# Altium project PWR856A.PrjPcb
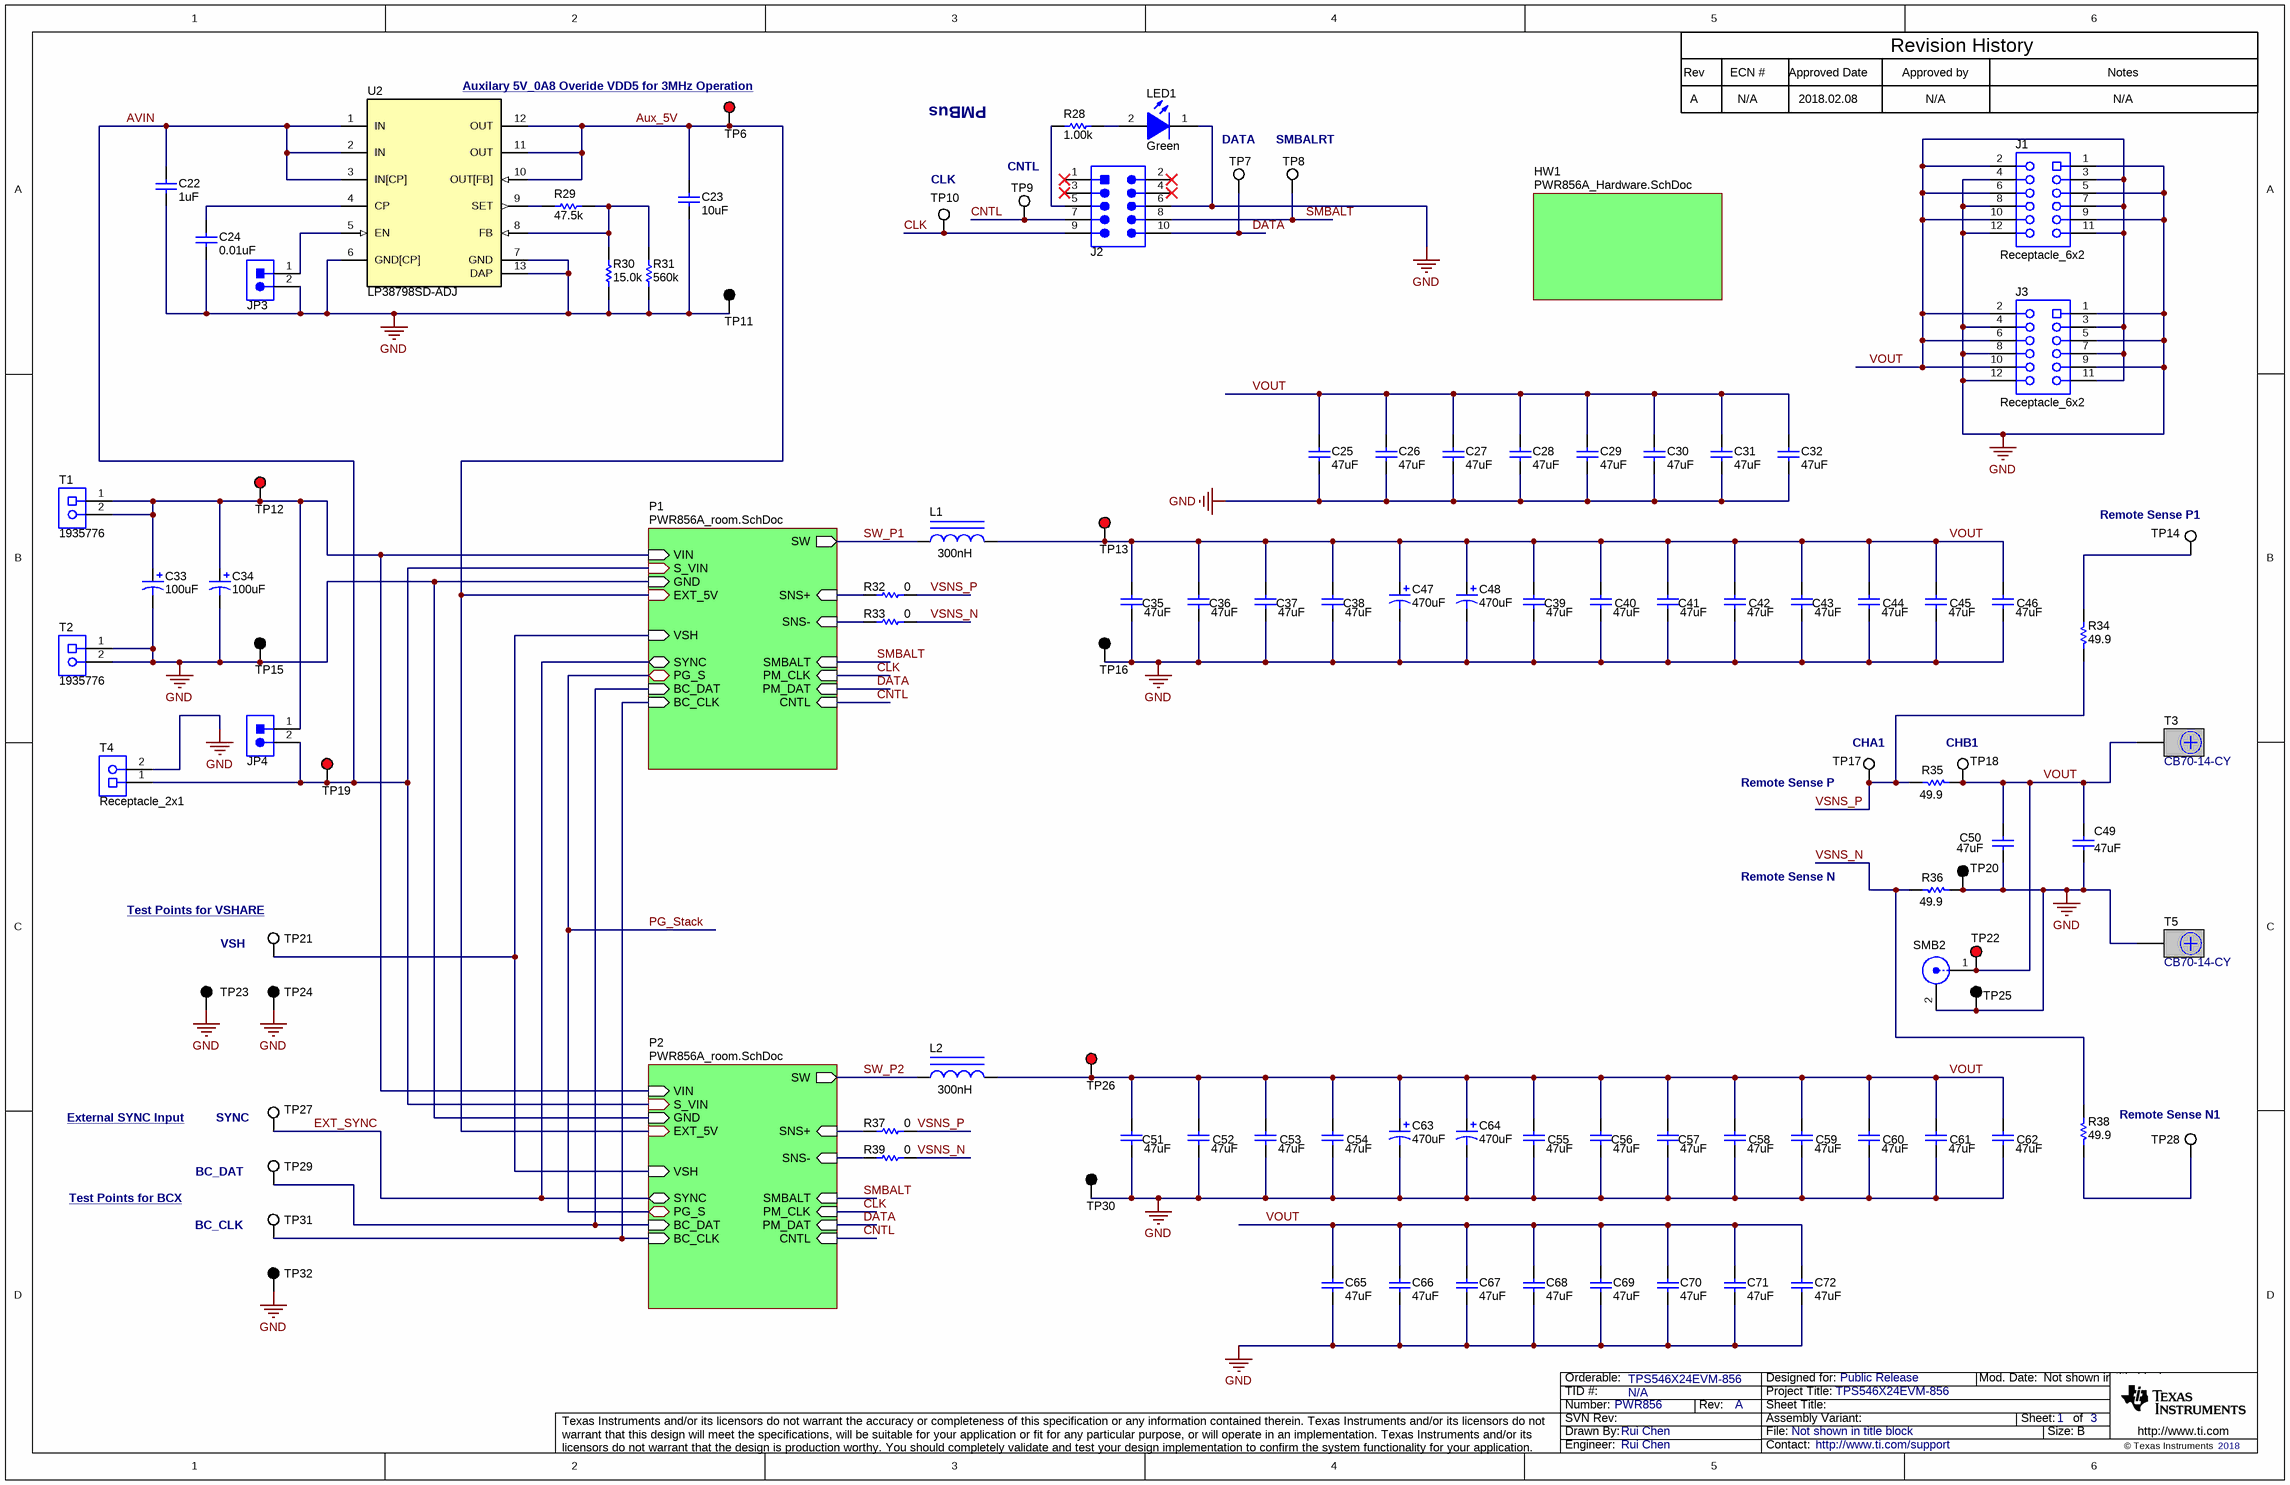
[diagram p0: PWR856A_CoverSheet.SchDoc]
CopyrightYear: 2018; EVM_orderable: TPS546X24EVM-856; PCB_Layout: Rui Chen; PCB_Rev: A; PRJ_Customer: Public Release; PRJ_Engineer: Rui Chen; PRJ_Number: PWR856; PRJ_Title: TPS546X24EVM-856; SCH_Rev: A; TechSupport: http://www.ti.com/support; TID: N/A
3 sheets, 253 parts. Net scope: strictly hierarchical (ports join the sheet entries above them; power ports are local).
Board file: PWR856A.PcbDoc
Sheets:
  PWR856A_CoverSheet.SchDoc
    P1 = PWR856A_room.SchDoc
    P2 = PWR856A_room.SchDoc
    HW1 = PWR856A_Hardware.SchDoc

## Sheet PWR856A_CoverSheet.SchDoc
size 431 x 279 mm; Date: Not shown in title block; ApprovedBy: Not shown in title block; CheckedBy: Not shown in title block; Author: Not shown in title block; CompanyName: Not shown in title block; DrawnBy: Rui Chen; Engineer: Not shown in title block; Organization: Not shown in title block; Address1: Not shown in title block; Address2: Not shown in title block; Address3: Not shown in title block; Address4: Not shown in title block; DocumentNumber: 1; Revision: Use project parameter SCH_Rev; SheetNumber: 1; SheetTotal: 3; PageSetup: Record=PageOptions¦CenterHorizontal=True¦CenterVertical=True¦PrintScale=1.00¦XCorrection=1.00¦YCorrection=1.00¦PrintKind=0¦BorderSize=5000000¦LeftOffset=0¦BottomOffset=0¦Orientation=2¦PaperLength=1000¦PaperWidth=1000¦Scale=100¦PaperSource=15¦PrintQuality=600¦MediaType=1¦DitherType=10¦PaperKind=Letter¦PrintScaleMode=1

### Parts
C22  ValueDisplayed: 1uF  [0805_HV]  (hidden comment: Capacitor)
C23  ValueDisplayed: 10uF  [0805_HV]  (hidden comment: Capacitor)
C24  ValueDisplayed: 0.01uF  [0603L]  (hidden comment: Capacitor)
C25  ValueDisplayed: 47uF  [1210_270]  (hidden comment: Capacitor)
C26  ValueDisplayed: 47uF  [1210_270]  (hidden comment: Capacitor)
C27  ValueDisplayed: 47uF  [1210_270]  (hidden comment: Capacitor)
C28  ValueDisplayed: 47uF  [1210_270]  (hidden comment: Capacitor)
C29  ValueDisplayed: 47uF  [1210_270]  (hidden comment: Capacitor)
C30  ValueDisplayed: 47uF  [1210_270]  (hidden comment: Capacitor)
C31  ValueDisplayed: 47uF  [1210_270]  (hidden comment: Capacitor)
C32  ValueDisplayed: 47uF  [1210_270]  (hidden comment: Capacitor)
C33  ValueDisplayed: 100uF  [SM_RADIAL_G]  (hidden comment: Cap_Polarized)
C34  ValueDisplayed: 100uF  [SM_RADIAL_G]  (hidden comment: Cap_Polarized)
C35  ValueDisplayed: 47uF  [1210_270]  (hidden comment: Capacitor)
C36  ValueDisplayed: 47uF  [1210_270]  (hidden comment: Capacitor)
C37  ValueDisplayed: 47uF  [1210_270]  (hidden comment: Capacitor)
C38  ValueDisplayed: 47uF  [1210_270]  (hidden comment: Capacitor)
C39  ValueDisplayed: 47uF  [1210_270]  (hidden comment: Capacitor)
C40  ValueDisplayed: 47uF  [1210_270]  (hidden comment: Capacitor)
C41  ValueDisplayed: 47uF  [1210_270]  (hidden comment: Capacitor)
C42  ValueDisplayed: 47uF  [1210_270]  (hidden comment: Capacitor)
C43  ValueDisplayed: 47uF  [1210_270]  (hidden comment: Capacitor)
C44  ValueDisplayed: 47uF  [1210_270]  (hidden comment: Capacitor)
C45  ValueDisplayed: 47uF  [1210_270]  (hidden comment: Capacitor)
C46  ValueDisplayed: 47uF  [1210_270]  (hidden comment: Capacitor)
C47  ValueDisplayed: 470uF  [7343-40]  (hidden comment: Cap_Polarized)
C48  ValueDisplayed: 470uF  [7343-40]  (hidden comment: Cap_Polarized)
C49  ValueDisplayed: 47uF  [1210_270]  (hidden comment: Capacitor)
C50  ValueDisplayed: 47uF  [1210_270]  (hidden comment: Capacitor)
C51  ValueDisplayed: 47uF  [1210_270]  (hidden comment: Capacitor)
C52  ValueDisplayed: 47uF  [1210_270]  (hidden comment: Capacitor)
C53  ValueDisplayed: 47uF  [1210_270]  (hidden comment: Capacitor)
C54  ValueDisplayed: 47uF  [1210_270]  (hidden comment: Capacitor)
C55  ValueDisplayed: 47uF  [1210_270]  (hidden comment: Capacitor)
C56  ValueDisplayed: 47uF  [1210_270]  (hidden comment: Capacitor)
C57  ValueDisplayed: 47uF  [1210_270]  (hidden comment: Capacitor)
C58  ValueDisplayed: 47uF  [1210_270]  (hidden comment: Capacitor)
C59  ValueDisplayed: 47uF  [1210_270]  (hidden comment: Capacitor)
C60  ValueDisplayed: 47uF  [1210_270]  (hidden comment: Capacitor)
C61  ValueDisplayed: 47uF  [1210_270]  (hidden comment: Capacitor)
C62  ValueDisplayed: 47uF  [1210_270]  (hidden comment: Capacitor)
C63  ValueDisplayed: 470uF  [7343-40]  (hidden comment: Cap_Polarized)
C64  ValueDisplayed: 470uF  [7343-40]  (hidden comment: Cap_Polarized)
C65  ValueDisplayed: 47uF  [1210_270]  (hidden comment: Capacitor)
C66  ValueDisplayed: 47uF  [1210_270]  (hidden comment: Capacitor)
C67  ValueDisplayed: 47uF  [1210_270]  (hidden comment: Capacitor)
C68  ValueDisplayed: 47uF  [1210_270]  (hidden comment: Capacitor)
C69  ValueDisplayed: 47uF  [1210_270]  (hidden comment: Capacitor)
C70  ValueDisplayed: 47uF  [1210_270]  (hidden comment: Capacitor)
C71  ValueDisplayed: 47uF  [1210_270]  (hidden comment: Capacitor)
C72  ValueDisplayed: 47uF  [1210_270]  (hidden comment: Capacitor)
J1  Receptacle_6x2  [Samtec_SSW-106-23-x-D]
J2  Header_5x2  [CONN_5103308-1]  (value not drawn)
J3  Receptacle_6x2  [Samtec_SSW-106-23-x-D]
JP3  Header_2x1  [TE_5-146278-2]  (value not drawn)
JP4  Header_2x1  [TE_5-146278-2]  (value not drawn)
L1  value 300nH  [SLC1480]  (hidden comment: Inductor_Iron)
L2  value 300nH  [SLC1480]  (hidden comment: Inductor_Iron)
LED1  value Green  [WL-SMCW_GREEN]  (hidden comment: LED_A2_K1)
R28  ValueDisplayed: 1.00k  [0603L]  (hidden comment: Resistor)
R29  ValueDisplayed: 47.5k  [0603L]  (hidden comment: Resistor)
R30  ValueDisplayed: 15.0k  [0603L]  (hidden comment: Resistor)
R31  ValueDisplayed: 560k  [0603L]  (hidden comment: Resistor)
R32  value 0  [0603L]  (hidden comment: Resistor)
R33  value 0  [0603L]  (hidden comment: Resistor)
R34  value 49.9  [0603L]  (hidden comment: Resistor)
R35  value 49.9  [0603L]  (hidden comment: Resistor)
R36  value 49.9  [0603L]  (hidden comment: Resistor)
R37  value 0  [0603L]  (hidden comment: Resistor)
R38  value 49.9  [0603L]  (hidden comment: Resistor)
R39  value 0  [0603L]  (hidden comment: Resistor)
SMB2  SMA_Contact1_GND2  [JAE_SMBR004D00]  (value not drawn)
T1  1935776  [Phoenix_1935776]
T2  1935776  [Phoenix_1935776]
T3  CB70-14-CY  [CB70-14-CY]
T4  Receptacle_2x1  [TERM_BLK_ED555-2DS]
T5  CB70-14-CY  [CB70-14-CY]
TP6  5010  [Keystone5010]  (value not drawn)
TP7  5012  [Keystone5012]  (value not drawn)
TP8  5012  [Keystone5012]  (value not drawn)
TP9  5012  [Keystone5012]  (value not drawn)
TP10  5012  [Keystone5012]  (value not drawn)
TP11  5011  [Keystone5011]  (value not drawn)
TP12  5010  [Keystone5010]  (value not drawn)
TP13  5010  [Keystone5010]  (value not drawn)
TP14  5010  [Keystone5012]  (value not drawn)
TP15  5011  [Keystone5011]  (value not drawn)
TP16  5011  [Keystone5011]  (value not drawn)
TP17  5012  [Keystone5012]  (value not drawn)
TP18  5012  [Keystone5012]  (value not drawn)
TP19  5010  [Keystone5010]  (value not drawn)
TP20  5011  [Keystone5011]  (value not drawn)
TP21  5012  [Keystone5012]  (value not drawn)
TP22  5012  [Keystone5010]  (value not drawn)
TP23  5011  [Keystone5011]  (value not drawn)
TP24  5011  [Keystone5011]  (value not drawn)
TP25  5011  [Keystone5011]  (value not drawn)
TP26  5010  [Keystone5010]  (value not drawn)
TP27  5012  [Keystone5012]  (value not drawn)
TP28  5011  [Keystone5012]  (value not drawn)
TP29  5012  [Keystone5012]  (value not drawn)
TP30  5011  [Keystone5011]  (value not drawn)
TP31  5012  [Keystone5012]  (value not drawn)
TP32  5011  [Keystone5011]  (value not drawn)
U2  LP38798SD-ADJ  [DNT0012B]

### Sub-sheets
HW1 = PWR856A_Hardware.SchDoc: no entries
P1 = PWR856A_room.SchDoc: SNS+ (in), SMBALT (in), PM_CLK (in), PM_DAT (in), BC_CLK (in), BC_DAT (in), VIN, GND, SNS- (in), SW, VSH (in), SYNC (bidir), CNTL (in), S_VIN, EXT_5V (in), PG_S (bidir)
P2 = PWR856A_room.SchDoc: SNS+ (in), SMBALT (in), PM_CLK (in), PM_DAT (in), BC_CLK (in), BC_DAT (in), VIN, GND, SNS- (in), SW, VSH (in), SYNC (bidir), CNTL (in), S_VIN, EXT_5V (in), PG_S (bidir)

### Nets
GND: C22.2 C23.2 C24.2 C25.2 C26.2 C27.2 C28.2 C29.2 C30.2 C31.2 C32.2 C33.2(-) C34.2(-) C35.1 C36.1 C37.1 C38.1 C39.1 C40.1 C41.1 C42.1 C43.1 C44.1 C45.1 C46.1 C47.2(-) C48.2(-) C49.1 C50.1 C51.1 C52.1 C53.1 C54.1 C55.1 C56.1 C57.1 C58.1 C59.1 C60.1 C61.1 C62.1 C63.2(-) C64.2(-) C65.2 C66.2 C67.2 C68.2 C69.2 C70.2 C71.2 C72.2 J1.1 J1.4 J1.5 J1.8 J1.9 J1.12 J2.6 J3.1 J3.4 J3.5 J3.8 J3.9 J3.12 JP3.2 LED1.1(K) R30.1 R31.1 R36.1 SMB2.2 T2.1 T2.2 T4.2 T5.1 TP11.1 TP15.1 TP16.1 TP20.1 TP23.1 TP24.1 TP25.1 TP30.1 TP32.1 U2.6(GND[CP]) U2.7(GND) U2.13(DAP) ; sheet P1/GND, sheet P2/GND
Aux_5V: C23.1 TP6.1 U2.10(OUT[FB]) U2.11(OUT) U2.12(OUT) ; sheet P1/EXT_5V, sheet P2/EXT_5V
AVIN: C22.1 JP4.2 T4.1 TP19.1 U2.1(IN) U2.2(IN) U2.3(IN[CP]) ; sheet P1/S_VIN, sheet P2/S_VIN
CLK: J2.9 TP10.1 ; sheet P1/PM_CLK, sheet P2/PM_CLK
CNTL: J2.7 TP9.1 ; sheet P1/CNTL, sheet P2/CNTL
DATA: J2.10 TP7.1 ; sheet P1/PM_DAT, sheet P2/PM_DAT
EXT_SYNC: TP27.1 ; sheet P1/SYNC, sheet P2/SYNC
PG_Stack: sheet P1/PG_S, sheet P2/PG_S
PVIN: C33.1(+) C34.1(+) JP4.1 T1.1 T1.2 TP12.1 ; sheet P1/VIN, sheet P2/VIN
SMBALT: J2.8 TP8.1 ; sheet P1/SMBALT, sheet P2/SMBALT
SW_P1: L1.1 ; sheet P1/SW
SW_P2: L2.1 ; sheet P2/SW
VOUT: C25.1 C26.1 C27.1 C28.1 C29.1 C30.1 C31.1 C32.1 C35.2 C36.2 C37.2 C38.2 C39.2 C40.2 C41.2 C42.2 C43.2 C44.2 C45.2 C46.2 C47.1(+) C48.1(+) C49.2 C50.2 C51.2 C52.2 C53.2 C54.2 C55.2 C56.2 C57.2 C58.2 C59.2 C60.2 C61.2 C62.2 C63.1(+) C64.1(+) C65.1 C66.1 C67.1 C68.1 C69.1 C70.1 C71.1 C72.1 J1.2 J1.3 J1.6 J1.7 J1.10 J1.11 J3.2 J3.3 J3.6 J3.7 J3.10 J3.11 L1.2 L2.2 R35.1 SMB2.1 T3.1 TP13.1 TP18.1 TP22.1 TP26.1
VSNS_N: R33.2 R36.2 R38.1 R39.2
VSNS_P: R32.2 R34.2 R35.2 R37.2 TP17.1
NetC17_P1_1: R32.1 ; sheet P1/SNS+
NetC17_P1_2: R33.1 ; sheet P1/SNS-
NetC17_P2_1: R37.1 ; sheet P2/SNS+
NetC17_P2_2: R39.1 ; sheet P2/SNS-
NetC24_1: C24.1 U2.4(CP)
NetJ2_5: J2.5 R28.1
NetJP3_1: JP3.1 U2.5(EN)
NetLED1_2: LED1.2(A) R28.2
NetR15_P1_1: TP21.1 ; sheet P1/VSH, sheet P2/VSH
NetR16_P1_2: TP31.1 ; sheet P1/BC_CLK, sheet P2/BC_CLK
NetR22_P1_2: TP29.1 ; sheet P1/BC_DAT, sheet P2/BC_DAT
NetR29_1: R29.1 R30.2 R31.2 U2.8(FB)
NetR29_2: R29.2 U2.9(SET)
NetR34_1: R34.1 TP14.1
NetR38_2: R38.2 TP28.1

Not connected (* = marked no-connect by the designer): J2 1* 2* 3* 4*

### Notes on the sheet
- Auxilary 5V_0A8 Overide VDD5 for 3MHz Operation
- Rev
- A
- ECN #
- N/A
- Approved Date
- 2018.02.08
- Approved by
- Revision History
- Notes
- PMBus
- CNTL
- DATA
- (near TP8) SMBALRT
- (near TP10) CLK
- (near TP14) Remote Sense P1
- (near TP17) CHA1
- CHB1
- (near TP17) Remote Sense P
- Remote Sense N
- (near TP21) Test Points for VSHARE
- VSH
- External SYNC Input
- (near TP29) BC_DAT
- (near TP27) SYNC
- (near TP28) Remote Sense N1
- Test Points for BCX
- (near TP31) BC_CLK

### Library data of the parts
C22 = CMP-0008350-2: CAP, CERM, 1 uF, 50 V, +/- 10%, X7R, 0805; PartNumber: GRM21BR71H105KA12L; Manufacturer: MuRata; Polarized: N; Value: 1uF; U/M: EA; Cap_F: 1µF; Value1: Unknown; VDC_V: 50V; TaMin_C: -55°C; TaMax_C: 125°C; Cap_Case: 0805; SizeArea_mm2: 2.5; SizeAreaWB_mm2: 6.75; SizeX_mm: 2; SizeY_mm: 1.25; SizeZ_mm: 1.45; AEC Category: Q200
C23 = CMP-0008316-2: CAP, CERM, 10 uF, 10 V, +/- 20%, X7R, 0805; PartNumber: GRM21BR71A106ME51L; Manufacturer: MuRata; Polarized: N; Value: 10uF; U/M: EA; Cap_F: 10µF; Value1: Unknown; VDC_V: 10V; TaMin_C: -55°C; TaMax_C: 125°C; Cap_Case: 0805; SizeArea_mm2: 2.5; SizeAreaWB_mm2: 6.75; SizeX_mm: 2; SizeY_mm: 1.25; SizeZ_mm: 1.45; AEC Category: Q200
C24 = CMP-0007403-4: CAP, CERM, 0.01 uF, 25 V, +/- 10%, X7R, 0603; PartNumber: GRM188R71E103KA01D; Manufacturer: MuRata; Polarized: N; Value: 0.01uF; U/M: EA; Cap_F: 10nF; Value1: Unknown; VDC_V: 25V; TaMin_C: -55°C; TaMax_C: 125°C; Cap_Case: 0603; SizeArea_mm2: 1.28; SizeAreaWB_mm2: 4.68; SizeX_mm: 1.6; SizeY_mm: 0.8; SizeZ_mm: 1; AEC Category: Q200
C25-C32 C35-C46 C49-C62 C65-C72 = CMP-0009220-2: CAP, CERM, 47 uF, 10 V, +/- 10%, X7R, 1210; PartNumber: GRM32ER71A476KE15L; Manufacturer: MuRata; U/M: EA; Cap_F: 47µF; Value: 47uF; Value1: Unknown; VDC_V: 10V; TaMin_C: -55°C; TaMax_C: 125°C; Polarized: N; Cap_Case: 1210; SizeArea_mm2: 8; SizeAreaWB_mm2: 14.7; SizeX_mm: 3.2; SizeY_mm: 2.5; SizeZ_mm: 2.7; AEC Category: Q200
C33 C34 = CMP-0010663-1: CAP, AL, 100 uF, 35 V, +/- 20%, 0.15 ohm, SMD; PartNumber: EEE-FC1V101P; Manufacturer: Panasonic; Polarized: Y; CompType: Capacitor; Value: 100uF; U/M: EA; Cap_F: 100µF; ESR_ohm: 1.5d; VDC_V: 35V; IRMS_A: 2.2dA; TaMin_C: -40°C; TaMax_C: 105°C; Cap_Case: G; AEC Category: Q200; SizeArea_mm2: 123.6; SizeAreaWB_mm2: 172.2; SizeX_mm: 12; SizeY_mm: 10.3; SizeZ_mm: 10.2
C47 C48 C63 C64 = CMP-0012642-3: CAP, Tantalum Polymer, 470 uF, 6.3 V, +/- 20%, 0.01 ohm, 7343-40 SMD; Manufacturer: Panasonic; PartNumber: 6TPF470MAH; CompType: Capacitor; Value: 470uF; Polarized: Y; Cap_F: 470µF; VDC_V: 6.3V; ESR_ohm: 0.01; IRMS_A: 4.4A; TaMin_C: -55°C; TaMax_C: 105°C; Cap_Case: D4; AEC Category: Q200; AEC Qualified: N; SizeArea_mm2: 31.39; SizeAreaWB_mm2: 58.59; SizeX_mm: 7.3; SizeY_mm: 4.3; SizeZ_mm: 4
J1 J3 = CMP-0055669-1: Receptacle, 2.54mm, 6x2, Gold, TH; PartNumber: SSW-106-23-F-D; Manufacturer: Samtec; CompType: Socket Strip; Pitch_mm: 2.54; Gender: Female; Row_Count: 2; Current_A: 5.7A; Voltage_V: 550V; Cert_CSA: Y; CNHeader: FALSE; CT: TRUE
J2 = CMP-0054834-1: Header (shrouded), 100mil, 5x2, Gold, TH; PartNumber: 5103308-1; Manufacturer: TE Connectivity; CNHeader: FALSE; Green_Lifecycle: Active; Green_REACh: Passed
JP3 JP4 = CMP-0054952-1: Header, 100mil, 2x1, Tin, TH; PartNumber: 5-146278-2; Manufacturer: TE Connectivity; CNHeader: TRUE; CT: FALSE; Green_Lifecycle: Active; Green_REACh: Passed
L1 L2 = CMP-0060889-1: Inductor, Shielded, Ferrite, 300 nH, 52 A, 0.00015 ohm, SMD; PartNumber: SLC1480-301MLB; Manufacturer: Coilcraft; Imax_A: 52A; Irms: 55A @ 40C rise; Isat: 52A @ 30% inductance drop; DCR_ohm: 150µ; AEC Category: Q200; Green_Lifecycle: Not Set; Green_REACh: Incomplete; SizeArea_mm2: 174.307; SizeAreaWB_mm2: 231.127; SizeX_mm: 13.46; SizeY_mm: 12.95; SizeZ_mm: 8
LED1 = CMP-0002905-1: LED, Green, SMD; Manufacturer: Wurth Elektronik; PartNumber: 150060GS75000; Type: InGaN; Vf_V: 3.2V; Io_A: 20mA; Tjmax_C: 85°C; Value1: W; Angle: 140; U/M: EA
R28 = CMP-0022109-5: RES, 1.00 k, 1%, 0.1 W, AEC-Q200 Grade 0, 0603; PartNumber: CRCW06031K00FKEA; Manufacturer: Vishay-Dale; Value: 1.00k; Res_ohm: 1k; Value_Code: 1k00; Power_W: 100mW; Value2: 0.1W; VDC_V: 75V; TempCo: 100 ppm/C; EIA_Code: E96; AEC Category: Q200; AEC Grade: 0; AEC Qualified: Y; SizeArea_mm2: 1.28; SizeX_mm: 1.6; SizeY_mm: 0.8; SizeZ_mm: 1
R29 = CMP-0022439-4: RES, 47.5 k, 1%, 0.1 W, AEC-Q200 Grade 0, 0603; PartNumber: CRCW060347K5FKEA; Manufacturer: Vishay-Dale; Value: 47.5k; Value_Code: 47k5; Power_W: 100mW; Value2: 0.1W; VDC_V: 75V; TempCo: 100 ppm/C; SizeArea_mm2: 1.28; SizeX_mm: 1.6; SizeY_mm: 0.8; SizeZ_mm: 1; EIA_Code: E96; AEC Category: Q200; AEC Qualified: Y; AEC Grade: 0
R30 = CMP-0022066-4: RES, 15.0 k, 1%, 0.1 W, AEC-Q200 Grade 0, 0603; PartNumber: CRCW060315K0FKEA; Manufacturer: Vishay-Dale; Value: 15.0k; Res_ohm: 15k; Value_Code: 15k0; Power_W: 100mW; Value2: 0.1W; VDC_V: 75V; TempCo: 100 ppm/C; SizeArea_mm2: 1.28; SizeX_mm: 1.6; SizeY_mm: 0.8; SizeZ_mm: 1; EIA_Code: E96; AEC Category: Q200; AEC Qualified: Y; AEC Grade: 0
R31 = CMP-0023182-2: RES, 560 k, 1%, 0.1 W, 0603; PartNumber: RC0603FR-07560KL; Manufacturer: Yageo America; Value: 560k; Power_W: 100mW; Value2: 0.1W; VDC_V: 150V; TempCo: 200 ppm/C; SizeArea_mm2: 1.28; SizeX_mm: 1.6; SizeY_mm: 0.8; SizeZ_mm: 1; U/M: EA; AEC Category: Q200
R32 R33 R37 R39 = CMP-0025874-3: RES, 0, 5%, 0.1 W, 0603; PartNumber: ERJ-3GEY0R00V; Manufacturer: Panasonic; Value_Code: 0000; Power_W: 100mW; Value2: 0.1W; VDC_V: 50V; TempCo: 600 ppm/C; EIA_Code: E24; U/M: EA; AEC Category: Q200; SizeArea_mm2: 1.28; SizeX_mm: 1.6; SizeY_mm: 0.8; SizeZ_mm: 1
R34-R36 R38 = CMP-0022448-4: RES, 49.9, 1%, 0.1 W, AEC-Q200 Grade 0, 0603; PartNumber: CRCW060349R9FKEA; Manufacturer: Vishay-Dale; Value_Code: 49R9; Power_W: 100mW; Value2: 0.1W; VDC_V: 75V; TempCo: 100 ppm/C; EIA_Code: E96; AEC Category: Q200; AEC Grade: 0; AEC Qualified: Y; SizeArea_mm2: 1.28; SizeX_mm: 1.6; SizeY_mm: 0.8; SizeZ_mm: 1
SMB2 = CMP-0075106-1: Connector, Receptacle, 50 ohm, TH; PartNumber: SMBR004D00; Manufacturer: JAE Electronics; CNHeader: False
T1 T2 = CMP-0055506-1: Terminal Block, 2x1, 5mm, Green, TH; Manufacturer: Phoenix Contact; Pitch_mm: 5; Gender: Female; Row_Count: 1; CNHeader: FALSE; Green_Lifecycle: Not Set; Green_REACh: Incomplete; CT: TRUE
T3 T5 = CMP-0055443-1: Terminal 90A Lug; Manufacturer: Panduit; CNHeader: FALSE; Green_Lifecycle: Not Set; Cert_CULUS: Y; Green_REACh: Incomplete; Voltage_V: 600V; CompType: Screw Terminal; ContactFinish: Copper
T4 = CMP-0074913-1: Terminal Block, 3.5mm Pitch, 2x1, TH; PartNumber: ED555/2DS; Manufacturer: On-Shore Technology; Pitch_mm: 3.5; Gender: Female; Shrouded: N; Row_Count: 1; ContactFinish: Brass; Color: Grey; Current_A: 6A; Voltage_V: 150V; Cert_CULUS: Y; CNHeader: False; CT: True; Green_Lifecycle: Active; Green_REACh: Passed
TP6 TP12 TP13 TP19 TP22 TP26 = CMP-0055147-1: Test Point, Multipurpose, Red, TH; Manufacturer: Keystone; ContactFinish: Silver; CNHeader: FALSE; CT: TRUE; Green_Lifecycle: Active; Green_REACh: Passed
TP7-TP10 TP14 TP17 TP18 TP21 TP27-TP29 TP31 = CMP-0055149-1: Test Point, Multipurpose, White, TH; Manufacturer: Keystone; ContactFinish: Silver; CNHeader: FALSE; CT: TRUE; Green_Lifecycle: Active; Green_REACh: Passed
TP11 TP15 TP16 TP20 TP24 TP25 TP30 TP32 = CMP-0055148-1: Test Point, Multipurpose, Black, TH; Manufacturer: Keystone; ContactFinish: Silver; CNHeader: FALSE; CT: TRUE; Green_Lifecycle: Active; Green_REACh: Passed
TP23 = CMP-0055148-1: Test Point, Multipurpose, Black, TH; Manufacturer: Keystone; ContactFinish: Silver; Green_Lifecycle: Active; Green_REACh: Passed; CNHeader: FALSE; CT: TRUE
U2 = CMP-0066007-2: 800-mA Ultra-Low-Noise, High-PSRR LDO, DNT0012B (WSON-12); PartNumber: LP38798SD-ADJ/NOPB; Manufacturer: Texas Instruments; SizeArea_mm2: 16.0; SizeAreaWB_mm2: 25.0; SizeX_mm: 4.0; SizeZ_mm: 0.8; CompType: IC; U/M: EA

## Sheet PWR856A_room.SchDoc
size 431 x 279 mm; Date: Not shown in title block; ApprovedBy: Not shown in title block; CheckedBy: Not shown in title block; Author: Not shown in title block; CompanyName: Not shown in title block; DrawnBy: Rui Chen; Engineer: Not shown in title block; Organization: Not shown in title block; Address1: Not shown in title block; Address2: Not shown in title block; Address3: Not shown in title block; Address4: Not shown in title block; DocumentNumber: 1; Revision: Use project parameter SCH_Rev; SheetNumber: 2; SheetTotal: 3; PageSetup: Record=PageOptions¦CenterHorizontal=True¦CenterVertical=True¦PrintScale=1.00¦XCorrection=1.00¦YCorrection=1.00¦PrintKind=0¦BorderSize=5000000¦LeftOffset=0¦BottomOffset=0¦Orientation=2¦PaperLength=1000¦PaperWidth=1000¦Scale=100¦PaperSource=15¦PrintQuality=600¦MediaType=1¦DitherType=10¦PaperKind=Letter¦PrintScaleMode=1
Used 2 times, as channels P1, P2. Parts and nets are listed once, with the designators drawn on the sheet.
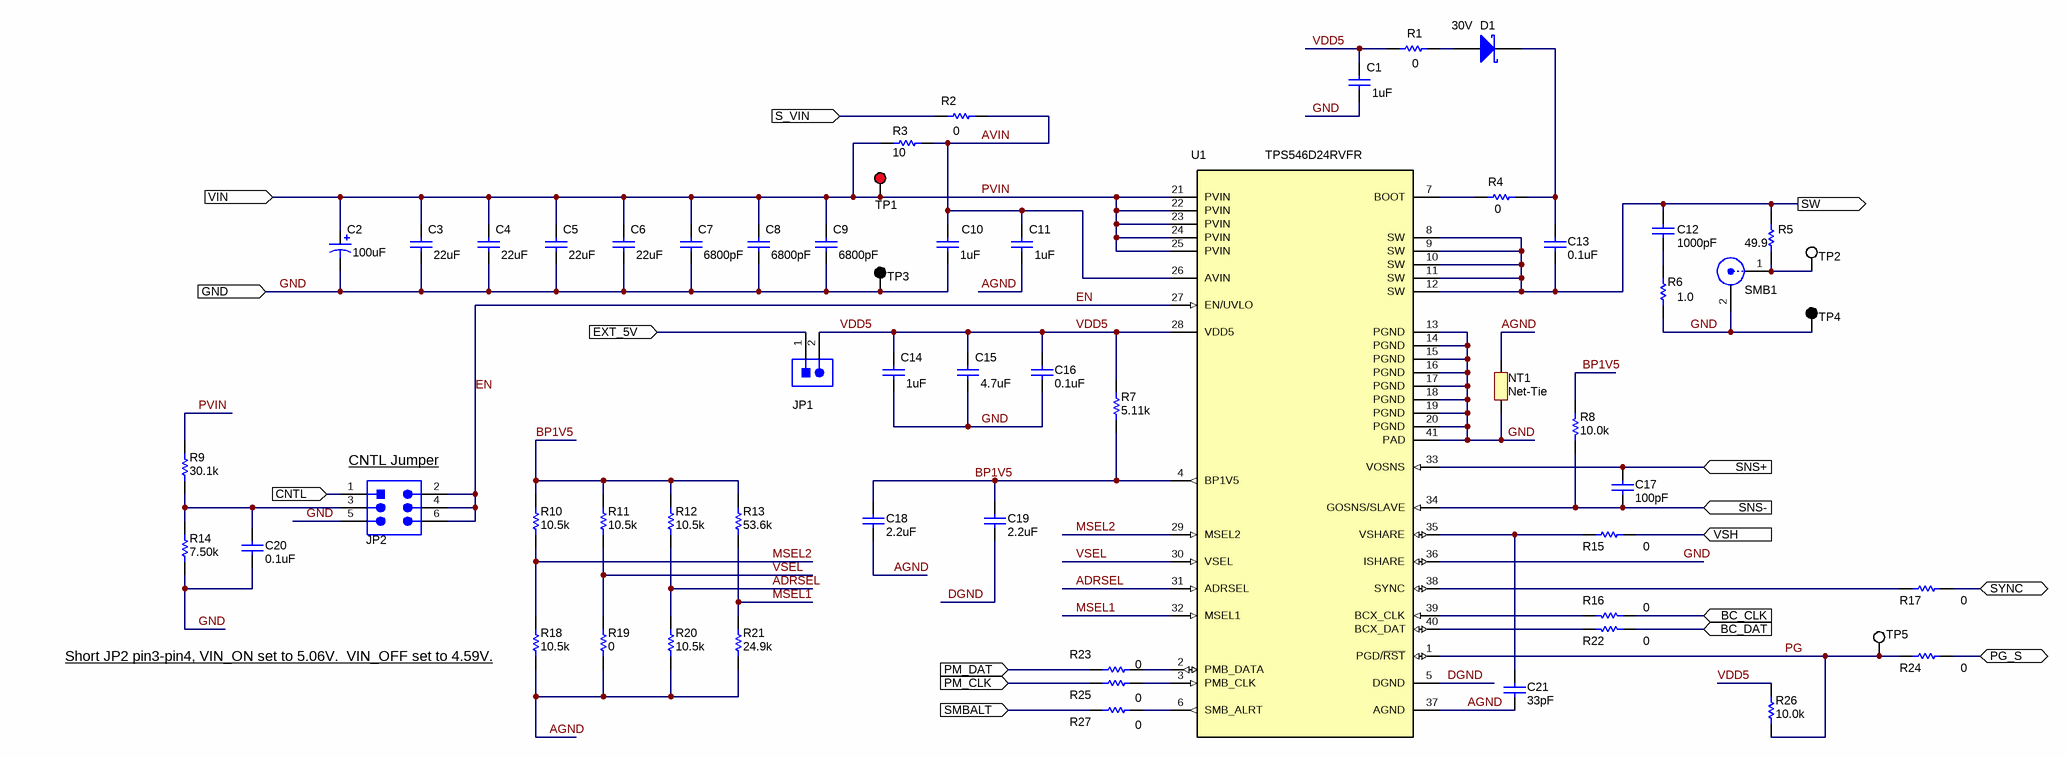
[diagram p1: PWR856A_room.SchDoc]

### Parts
C1  ValueDisplayed: 1uF  [0603L]  (hidden comment: Capacitor)
C2  ValueDisplayed: 100uF  [SM_RADIAL_G]  (hidden comment: Cap_Polarized)
C3  ValueDisplayed: 22uF  [1210_270]  (hidden comment: Capacitor)
C4  ValueDisplayed: 22uF  [1210_270]  (hidden comment: Capacitor)
C5  ValueDisplayed: 22uF  [1210_270]  (hidden comment: Capacitor)
C6  ValueDisplayed: 22uF  [1210_270]  (hidden comment: Capacitor)
C7  ValueDisplayed: 6800pF  [0402]  (hidden comment: Capacitor)
C8  ValueDisplayed: 6800pF  [0402]  (hidden comment: Capacitor)
C9  ValueDisplayed: 6800pF  [0402]  (hidden comment: Capacitor)
C10  ValueDisplayed: 1uF  [0603L]  (hidden comment: Capacitor)
C11  ValueDisplayed: 1uF  [0603L]  (hidden comment: Capacitor)
C12  ValueDisplayed: 1000pF  [0603L]  (hidden comment: Capacitor)
C13  ValueDisplayed: 0.1uF  [0603L]  (hidden comment: Capacitor)
C14  ValueDisplayed: 1uF  [0603L]  (hidden comment: Capacitor)
C15  ValueDisplayed: 4.7uF  [0603L]  (hidden comment: Capacitor)
C16  ValueDisplayed: 0.1uF  [0603L]  (hidden comment: C0603C104K5RACTU)
C17  ValueDisplayed: 100pF  [0603L]  (hidden comment: Capacitor)
C18  ValueDisplayed: 2.2uF  [0603L]  (hidden comment: Capacitor)
C19  ValueDisplayed: 2.2uF  [0603L]  (hidden comment: GRM188Z71C225KE43)
C20  ValueDisplayed: 0.1uF  [0603L]  (hidden comment: C0603C104K5RACTU)
C21  ValueDisplayed: 33pF  [0603L]  (hidden comment: Capacitor)
D1  value 30V  [SOD-523]  (hidden comment: DIODE_SCHOTTKY)
JP1  Header_2x1  [Sullins_Gxx02SAAN]  (value not drawn)
JP2  Header_3x2  [Sullins_PBC03DAAN]  (value not drawn)
NT1  Net-Tie  [Net-Tie_10mil]  (net tie, no BOM)
R1  ValueDisplayed: 0  [0603L]  (hidden comment: Resistor)
R2  ValueDisplayed: 0  [0603L]  (hidden comment: Resistor)
R3  ValueDisplayed: 10  [0603L]  (hidden comment: CRCW060310R0JNEA)
R4  ValueDisplayed: 0  [0603L]  (hidden comment: Resistor)
R5  value 49.9  [0603L]  (hidden comment: Resistor)
R6  value 1.0  [1206]  (hidden comment: Resistor)
R7  ValueDisplayed: 5.11k  [0603L]  (hidden comment: RC0603FR-075K11L)
R8  ValueDisplayed: 10.0k  [0603L]  (hidden comment: Resistor)
R9  ValueDisplayed: 30.1k  [0603L]  (hidden comment: RC0603FR-0730K1L)
R10  ValueDisplayed: 10.5k  [0603L]  (hidden comment: Resistor)
R11  ValueDisplayed: 10.5k  [0603L]  (hidden comment: Resistor)
R12  ValueDisplayed: 10.5k  [0603L]  (hidden comment: Resistor)
R13  ValueDisplayed: 53.6k  [0603L]  (hidden comment: Resistor)
R14  ValueDisplayed: 7.50k  [0603L]  (hidden comment: ERJ-3EKF7501V)
R15  ValueDisplayed: 0  [0603L]  (hidden comment: Resistor)
R16  ValueDisplayed: 0  [0603L]  (hidden comment: Resistor)
R17  ValueDisplayed: 0  [0603L]  (hidden comment: Resistor)
R18  ValueDisplayed: 10.5k  [0603L]  (hidden comment: Resistor)
R19  ValueDisplayed: 0  [0603L]  (hidden comment: Resistor)
R20  ValueDisplayed: 10.5k  [0603L]  (hidden comment: Resistor)
R21  ValueDisplayed: 24.9k  [0603L]  (hidden comment: Resistor)
R22  ValueDisplayed: 0  [0603L]  (hidden comment: Resistor)
R23  ValueDisplayed: 0  [0603L]  (hidden comment: Resistor)
R24  ValueDisplayed: 0  [0603L]  (hidden comment: Resistor)
R25  ValueDisplayed: 0  [0603L]  (hidden comment: Resistor)
R26  ValueDisplayed: 10.0k  [0603L]  (hidden comment: Resistor)
R27  ValueDisplayed: 0  [0603L]  (hidden comment: Resistor)
SMB1  SMA_Contact1_GND2  [JAE_SMBR004D00]  (value not drawn)
TP1  5010  [Keystone5010]  (value not drawn)
TP2  5012  [Keystone5012]  (value not drawn)
TP3  5011  [Keystone5011]  (value not drawn)
TP4  5011  [Keystone5011]  (value not drawn)
TP5  5012  [Keystone5012]  (value not drawn)
U1  TPS546D24RVFR  [RVF0040A_NV]

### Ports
BC_CLK (in), BC_DAT (in), CNTL (in), EXT_5V (in), GND, PG_S (bidir), PM_CLK (in), PM_DAT (in), S_VIN, SMBALT (in), SNS+ (in), SNS- (in), SW, SYNC (bidir), VIN, VSH (in)

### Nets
ADRSEL: R12.2 R20.1 U1.31(ADRSEL)
AGND: C11.1 C18.2 C21.2 NT1.1 R18.2 R19.2 R20.2 R21.2 U1.37(AGND)
AVIN: C10.2 C11.2 R2.1 R3.1 U1.26(AVIN)
BC_CLK: R16.2 ; port BC_CLK
BC_DAT: R22.2 ; port BC_DAT
BP1V5: C18.1 C19.1 R7.2 R8.1 R10.1 R11.1 R12.1 R13.1 U1.4(BP1V5)
CNTL: JP2.1 ; port CNTL
DGND: C19.2 U1.5(DGND)
EN: JP2.2 JP2.4 JP2.6 U1.27(EN/UVLO)
EXT_5V: JP1.1 ; port EXT_5V
GND: C1.1 C2.2(-) C3.2 C4.2 C5.1 C6.1 C7.1 C8.1 C9.1 C10.1 C14.1 C15.1 C16.1 C20.2 JP2.5 NT1.2 R6.1 R14.2 SMB1.2 TP3.1 TP4.1 U1.13(PGND) U1.14(PGND) U1.15(PGND) U1.16(PGND) U1.17(PGND) U1.18(PGND) U1.19(PGND) U1.20(PGND) U1.36(ISHARE) U1.41(PAD) ; port GND
MSEL1: R13.2 R21.1 U1.32(MSEL1)
MSEL2: R10.2 R18.1 U1.29(MSEL2)
PG: R24.2 R26.2 TP5.1 U1.1(PGD/~{RST})
PG_S: R24.1 ; port PG_S
PM_CLK: R25.2 ; port PM_CLK
PM_DAT: R23.2 ; port PM_DAT
PVIN: C2.1(+) C3.1 C4.1 C5.2 C6.2 C7.2 C8.2 C9.2 R3.2 R9.2 TP1.1 U1.21(PVIN) U1.22(PVIN) U1.23(PVIN) U1.24(PVIN) U1.25(PVIN) ; port VIN
S_VIN: R2.2 ; port S_VIN
SMBALT: R27.2 ; port SMBALT
SNS+: C17.1 U1.33(VOSNS) ; port SNS+
SNS-: C17.2 R8.2 U1.34(GOSNS/SLAVE) ; port SNS-
SW: C12.1 C13.2 R5.2 U1.8(SW) U1.9(SW) U1.10(SW) U1.11(SW) U1.12(SW) ; port SW
SYNC: R17.1 ; port SYNC
VDD5: C1.2 C14.2 C15.2 C16.2 JP1.2 R1.1 R7.1 R26.1 U1.28(VDD5)
VSEL: R11.2 R19.1 U1.30(VSEL)
VSH: R15.1 ; port VSH
NetC12_2: C12.2 R6.2
NetC13_1: C13.1 D1.1(K) R4.1
NetC20_1: C20.1 JP2.3 R9.1 R14.1
NetC21_1: C21.1 R15.2 U1.35(VSHARE)
NetD1_2: D1.2(A) R1.2
NetR4_2: R4.2 U1.7(BOOT)
NetR5_1: R5.1 SMB1.1 TP2.1
NetR16_1: R16.1 U1.39(BCX_CLK)
NetR17_2: R17.2 U1.38(SYNC)
NetR22_1: R22.1 U1.40(BCX_DAT)
NetR23_1: R23.1 U1.2(PMB_DATA)
NetR25_1: R25.1 U1.3(PMB_CLK)
NetR27_1: R27.1 U1.6(SMB_ALRT)

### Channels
P1: designators end in _P1; ports BC_CLK=NetR16_P1_2 BC_DAT=NetR22_P1_2 CNTL=CNTL EXT_5V=Aux_5V GND=GND PG_S=PG_Stack PM_CLK=CLK PM_DAT=DATA S_VIN=AVIN SMBALT=SMBALT SNS+=NetC17_P1_1 SNS-=NetC17_P1_2 SW=SW_P1 SYNC=EXT_SYNC VIN=PVIN VSH=NetR15_P1_1
P2: designators end in _P2; ports BC_CLK=NetR16_P1_2 BC_DAT=NetR22_P1_2 CNTL=CNTL EXT_5V=Aux_5V GND=GND PG_S=PG_Stack PM_CLK=CLK PM_DAT=DATA S_VIN=AVIN SMBALT=SMBALT SNS+=NetC17_P2_1 SNS-=NetC17_P2_2 SW=SW_P2 SYNC=EXT_SYNC VIN=PVIN VSH=NetR15_P1_1

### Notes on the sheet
- (near JP2) CNTL Jumper
- (near R18) Short JP2 pin3-pin4, VIN_ON set to 5.06V.  VIN_OFF set to 4.59V.

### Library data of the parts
C1 C10 C11 C14 = CMP-0007405-4: CAP, CERM, 1 uF, 25 V, +/- 10%, X7R, 0603; PartNumber: GRM188R71E105KA12D; Manufacturer: MuRata; Polarized: N; Value: 1uF; U/M: EA; Cap_F: 1µF; Value1: Unknown; VDC_V: 25V; TaMin_C: -55°C; TaMax_C: 125°C; Cap_Case: 0603; AEC Category: Q200; SizeArea_mm2: 1.28; SizeAreaWB_mm2: 4.68; SizeX_mm: 1.6; SizeY_mm: 0.8; SizeZ_mm: 1
C2 = CMP-0010663-1: as C33 on sheet PWR856A_CoverSheet
C3-C6 = CMP-0009202-2: CAP, CERM, 22 uF, 25 V, +/- 10%, X6S, 1210; PartNumber: GRM32EC81E226KE15L; Manufacturer: MuRata; Polarized: N; Value: 22uF; U/M: EA; Cap_F: 22µF; Value1: Unknown; VDC_V: 25V; TaMin_C: -55°C; TaMax_C: 105°C; Cap_Case: 1210; SizeArea_mm2: 8; SizeAreaWB_mm2: 14.7; SizeX_mm: 3.2; SizeY_mm: 2.5; SizeZ_mm: 2.7; AEC Category: Q200
C7-C9 = CMP-0006696-2: CAP, CERM, 6800 pF, 50 V, +/- 10%, X7R, 0402; PartNumber: GRM155R71H682KA88D; Manufacturer: MuRata; Polarized: N; Value: 6800pF; U/M: EA; Cap_F: 6.8nF; Value1: Unknown; VDC_V: 50V; TaMin_C: -55°C; TaMax_C: 125°C; AEC Category: Q200; SizeArea_mm2: 0.5; SizeAreaWB_mm2: 3; SizeX_mm: 1; SizeZ_mm: 0.6
C12 = CMP-0006723-4: CAP, CERM, 1000 pF, 100 V, +/- 5%, X7R, 0603; PartNumber: 06031C102JAT2A; Manufacturer: AVX; Polarized: N; Value: 1000pF; U/M: EA; Cap_F: 1nF; ESR_ohm: 2.76d; Value1: 0.276 ohm; VDC_V: 100V; TaMin_C: -55°C; TaMax_C: 125°C; Cap_Case: 0603; AEC Category: Q200; SizeArea_mm2: 1.28; SizeAreaWB_mm2: 4.68; SizeX_mm: 1.6; SizeY_mm: 0.8; SizeZ_mm: 1
C13 = CMP-0006861-4: CAP, CERM, 0.1 uF, 50 V, +/- 10%, X7R, 0603; PartNumber: C0603C104K5RACTU; Manufacturer: Kemet; Polarized: N; Value: 0.1uF; U/M: EA; Cap_F: 100nF; Value1: Unknown; VDC_V: 50V; TaMin_C: -55°C; TaMax_C: 125°C; Cap_Case: 0603; AEC Category: Q200; SizeArea_mm2: 1.28; SizeAreaWB_mm2: 4.68; SizeX_mm: 1.6; SizeY_mm: 0.8; SizeZ_mm: 1
C15 = CMP-0006949-5: CAP, CERM, 4.7 uF, 10 V, +/- 10%, X5R, 0603; PartNumber: C0603C475K8PACTU; Manufacturer: Kemet; Polarized: N; Value: 4.7uF; U/M: EA; Cap_F: 4.7µF; ESR_ohm: 6m; Value1: 0.006 ohm; VDC_V: 10V; IRMS_A: 7.24A; TaMin_C: -55°C; TaMax_C: 85°C; Cap_Case: 0603; AEC Category: Q200; SizeArea_mm2: 1.28; SizeAreaWB_mm2: 4.68; SizeX_mm: 1.6; SizeY_mm: 0.8; SizeZ_mm: 1
C16 C20 = CMP-0006861-4: CAP, CERM, 0.1 uF, 50 V, +/- 10%, X7R, 0603; Manufacturer: Kemet; Polarized: N; Value: 0.1uF; U/M: EA; Cap_F: 100nF; Value1: Unknown; VDC_V: 50V; TaMin_C: -55°C; TaMax_C: 125°C; Cap_Case: 0603; AEC Category: Q200; SizeArea_mm2: 1.28; SizeAreaWB_mm2: 4.68; SizeX_mm: 1.6; SizeY_mm: 0.8; SizeZ_mm: 1
C17 = CMP-0007171-4: CAP, CERM, 100 pF, 50 V, +/- 5%, C0G/NP0, 0603; PartNumber: GRM1885C1H101JA01D; Manufacturer: MuRata; Polarized: N; Value: 100pF; U/M: EA; Value1: Unknown; VDC_V: 50V; TaMin_C: -55°C; TaMax_C: 125°C; Cap_Case: 0603; SizeArea_mm2: 1.28; SizeAreaWB_mm2: 4.68; SizeX_mm: 1.6; SizeY_mm: 0.8; SizeZ_mm: 1; AEC Category: Q200
C18 = CMP-0007499-4: CAP, CERM, 2.2 uF, 16 V, +/- 10%, X7R, 0603; PartNumber: GRM188Z71C225KE43; Manufacturer: MuRata; Polarized: N; Value: 2.2uF; U/M: EA; Cap_F: 2.2µF; Value1: Unknown; VDC_V: 16V; TaMin_C: -55°C; TaMax_C: 125°C; Cap_Case: 0603; SizeArea_mm2: 1.28; SizeAreaWB_mm2: 4.68; SizeX_mm: 1.6; SizeY_mm: 0.8; SizeZ_mm: 1; AEC Category: Q200
C19 = CMP-0007499-4: CAP, CERM, 2.2 uF, 16 V, +/- 10%, X7R, 0603; Manufacturer: MuRata; Polarized: N; Value: 2.2uF; U/M: EA; Cap_F: 2.2µF; Value1: Unknown; VDC_V: 16V; TaMin_C: -55°C; TaMax_C: 125°C; Cap_Case: 0603; SizeArea_mm2: 1.28; SizeAreaWB_mm2: 4.68; SizeX_mm: 1.6; SizeY_mm: 0.8; SizeZ_mm: 1; AEC Category: Q200
C21 = CMP-0006919-4: CAP, CERM, 33 pF, 50 V, +/- 5%, C0G/NP0, 0603; PartNumber: C0603C330J5GACTU; Manufacturer: Kemet; Polarized: N; Value: 33pF; U/M: EA; Value1: Unknown; VDC_V: 50V; TaMin_C: -55°C; TaMax_C: 125°C; Cap_Case: 0603; SizeArea_mm2: 1.28; SizeAreaWB_mm2: 4.68; SizeX_mm: 1.6; SizeY_mm: 0.8; SizeZ_mm: 1; AEC Category: Q200
D1 = CMP-0028846-2: Diode, Schottky, 30 V, 0.5 A, SOD-523; PartNumber: XBS053V15R-G; Manufacturer: Torex USA Corporation; U/M: EA; Vf_V: 4.7dV; Value1: 0.5A; Value2: 0.47V; Io_A: 5dA; TJmax_C: 125°C; SizeAreaWB_mm2: 5.13; SizeArea_mm2: 1.53; SizeX_mm: 1.7; SizeY_mm: 0.9; SizeZ_mm: 0.65; AEC Category: Q101; AEC Qualified: N; Green_Lifecycle: Not Set; Green_REACh: Incomplete
JP1 = CMP-0054576-1: Header, 2.54 mm, 2x1, Gold, TH; PartNumber: GBC02SAAN; Manufacturer: Sullins Connector Solutions; CNHeader: TRUE; CT: FALSE
JP2 = CMP-0054565-1: Header, 100mil, 3x2, Gold, TH; PartNumber: PBC03DAAN; Manufacturer: Sullins Connector Solutions; Pitch_mm: 2.54; Gender: Male; Shrouded: N; Row_Count: 2; Current_A: 3A; Voltage_V: 1.8kV; Cert_UL: Y; CNHeader: TRUE; CT: FALSE; Green_Lifecycle: Active; Green_REACh: Passed
NT1 = CMP-0078142-1: Single point connection between nets.
R1 R2 R4 R15-R17 R22-R25 R27 = CMP-0025874-3: RES, 0, 5%, 0.1 W, 0603; PartNumber: ERJ-3GEY0R00V; Manufacturer: Panasonic; Value: 0; Value_Code: 0000; Power_W: 100mW; Value2: 0.1W; VDC_V: 50V; TempCo: 600 ppm/C; EIA_Code: E24; U/M: EA; AEC Category: Q200; SizeArea_mm2: 1.28; SizeX_mm: 1.6; SizeY_mm: 0.8; SizeZ_mm: 1
R3 = CMP-0025703-4: RES, 10, 5%, 0.1 W, AEC-Q200 Grade 0, 0603; Manufacturer: Vishay-Dale; CompType: Resistor; Value: 10; Value_Code: 10R0; Power_W: 100mW; Value2: 0.1W; VDC_V: 75V; TempCo: 200 ppm/C; EIA_Code: E24; AEC Category: Q200; AEC Grade: 0; AEC Qualified: Y; SizeArea_mm2: 1.28; SizeX_mm: 1.6; SizeY_mm: 0.8; SizeZ_mm: 1
R5 = CMP-0022448-4: as R34 on sheet PWR856A_CoverSheet
R6 = CMP-0018617-3: RES, 1.0, 5%, 0.25 W, AEC-Q200 Grade 0, 1206; PartNumber: CRCW12061R00JNEA; Manufacturer: Vishay-Dale; Res_ohm: 1; Value_Code: 1R00; Power_W: 250mW; Value2: 0.25W; VDC_V: 200V; TempCo: 200 ppm/C; EIA_Code: E24; AEC Category: Q200; AEC Grade: 0; AEC Qualified: Y; SizeArea_mm2: 5.12; SizeX_mm: 3.2; SizeY_mm: 1.6; SizeZ_mm: 1.35
R7 = CMP-0023197-3: RES, 5.11 k, 1%, 0.1 W, 0603; Manufacturer: Yageo America; Value: 5.11k; Value_Code: 5k11; Power_W: 100mW; Value2: 0.1W; VDC_V: 150V; TempCo: 200 ppm/C; EIA_Code: E96; SizeArea_mm2: 1.28; SizeX_mm: 1.6; SizeY_mm: 0.8; SizeZ_mm: 1; AEC Category: Q200; U/M: EA
R8 R26 = CMP-0022746-3: RES, 10.0 k, 1%, 0.1 W, 0603; PartNumber: RC0603FR-0710KL; Manufacturer: Yageo America; Value: 10.0k; Res_ohm: 10k; Value_Code: 10k0; Power_W: 100mW; Value2: 0.1W; VDC_V: 150V; TempCo: 200 ppm/C; EIA_Code: E96; U/M: EA; AEC Category: Q200; SizeArea_mm2: 1.28; SizeX_mm: 1.6; SizeY_mm: 0.8; SizeZ_mm: 1
R9 = CMP-0023018-3: RES, 30.1 k, 1%, 0.1 W, 0603; Manufacturer: Yageo America; Value: 30.1k; Value_Code: 30k1; Power_W: 100mW; Value2: 0.1W; VDC_V: 150V; TempCo: 200 ppm/C; SizeArea_mm2: 1.28; SizeX_mm: 1.6; SizeY_mm: 0.8; SizeZ_mm: 1; EIA_Code: E96; U/M: EA; AEC Category: Q200
R10-R12 R18 R20 = CMP-0022000-4: RES, 10.5 k, 1%, 0.1 W, AEC-Q200 Grade 0, 0603; PartNumber: CRCW060310K5FKEA; Manufacturer: Vishay-Dale; Value: 10.5k; Value_Code: 10k5; Power_W: 100mW; Value2: 0.1W; VDC_V: 75V; TempCo: 100 ppm/C; EIA_Code: E96; SizeArea_mm2: 1.28; SizeX_mm: 1.6; SizeY_mm: 0.8; SizeZ_mm: 1; AEC Category: Q200; AEC Qualified: Y; AEC Grade: 0
R13 = CMP-0022490-4: RES, 53.6 k, 1%, 0.1 W, AEC-Q200 Grade 0, 0603; PartNumber: CRCW060353K6FKEA; Manufacturer: Vishay-Dale; Value: 53.6k; Value_Code: 53k6; Power_W: 100mW; Value2: 0.1W; VDC_V: 75V; TempCo: 100 ppm/C; EIA_Code: E96; SizeArea_mm2: 1.28; SizeX_mm: 1.6; SizeY_mm: 0.8; SizeZ_mm: 1; AEC Category: Q200; AEC Qualified: Y; AEC Grade: 0
R14 = CMP-0022708-3: RES, 7.50 k, 1%, 0.1 W, 0603; Manufacturer: Panasonic; Value: 7.50k; Res_ohm: 7.5k; Value_Code: 7k50; Power_W: 100mW; Value2: 0.1W; VDC_V: 75V; TempCo: 100 ppm/C; EIA_Code: E96; U/M: EA; SizeArea_mm2: 1.28; SizeX_mm: 1.6; SizeY_mm: 0.8; SizeZ_mm: 1; AEC Category: Q200
R19 = CMP-0025874-3: RES, 0, 5%, 0.1 W, 0603; PartNumber: ERJ-3GEY0R00V; Manufacturer: Panasonic; Value: 0; Value_Code: 0000; Power_W: 100mW; Value2: 0.1W; VDC_V: 50V; TempCo: 600 ppm/C; EIA_Code: E24; U/M: EA; SizeArea_mm2: 1.28; SizeX_mm: 1.6; SizeY_mm: 0.8; SizeZ_mm: 1; AEC Category: Q200
R21 = CMP-0022237-4: RES, 24.9 k, 1%, 0.1 W, AEC-Q200 Grade 0, 0603; PartNumber: CRCW060324K9FKEA; Manufacturer: Vishay-Dale; Value: 24.9k; Value_Code: 24k9; Power_W: 100mW; Value2: 0.1W; VDC_V: 75V; TempCo: 100 ppm/C; EIA_Code: E96; SizeArea_mm2: 1.28; SizeX_mm: 1.6; SizeY_mm: 0.8; SizeZ_mm: 1; AEC Category: Q200; AEC Qualified: Y; AEC Grade: 0
SMB1 = CMP-0075106-1: as SMB2 on sheet PWR856A_CoverSheet
TP1 = CMP-0055147-1: as TP6 on sheet PWR856A_CoverSheet
TP2 TP5 = CMP-0055149-1: as TP7 on sheet PWR856A_CoverSheet
TP3 TP4 = CMP-0055148-1: as TP11 on sheet PWR856A_CoverSheet
U1 = CMP-0014071-6: 2.95-16V 40A PMBUS Stackable Synchronous Buck Converter, RVF0040A (LQFN-CLIP-40); Alternate PartNumber: TPS546D24RVFT; Manufacturer: Texas Instruments; SizeArea_mm2: 35; SizeAreaWB_mm2: 63; SizeX_mm: 5; SizeY_mm: 7; SizeZ_mm: 1.52; CompType: IC; AEC Category: Q200; AEC Qualified: N

## Sheet PWR856A_Hardware.SchDoc
size 431 x 279 mm; Date: Not shown in title block; ApprovedBy: Not shown in title block; CheckedBy: Not shown in title block; Author: Not shown in title block; CompanyName: Not shown in title block; DrawnBy: Rui Chen; Engineer: Not shown in title block; Organization: Not shown in title block; Address1: Not shown in title block; Address2: Not shown in title block; Address3: Not shown in title block; Address4: Not shown in title block; DocumentNumber: 1; Revision: Use project parameter SCH_Rev; SheetNumber: 3; SheetTotal: 3; PageSetup: Record=PageOptions¦CenterHorizontal=True¦CenterVertical=True¦PrintScale=1.00¦XCorrection=1.00¦YCorrection=1.00¦PrintKind=0¦BorderSize=5000000¦LeftOffset=0¦BottomOffset=0¦Orientation=2¦PaperLength=1000¦PaperWidth=1000¦Scale=100¦PaperSource=15¦PrintQuality=600¦MediaType=1¦DitherType=10¦PaperKind=Letter¦PrintScaleMode=1
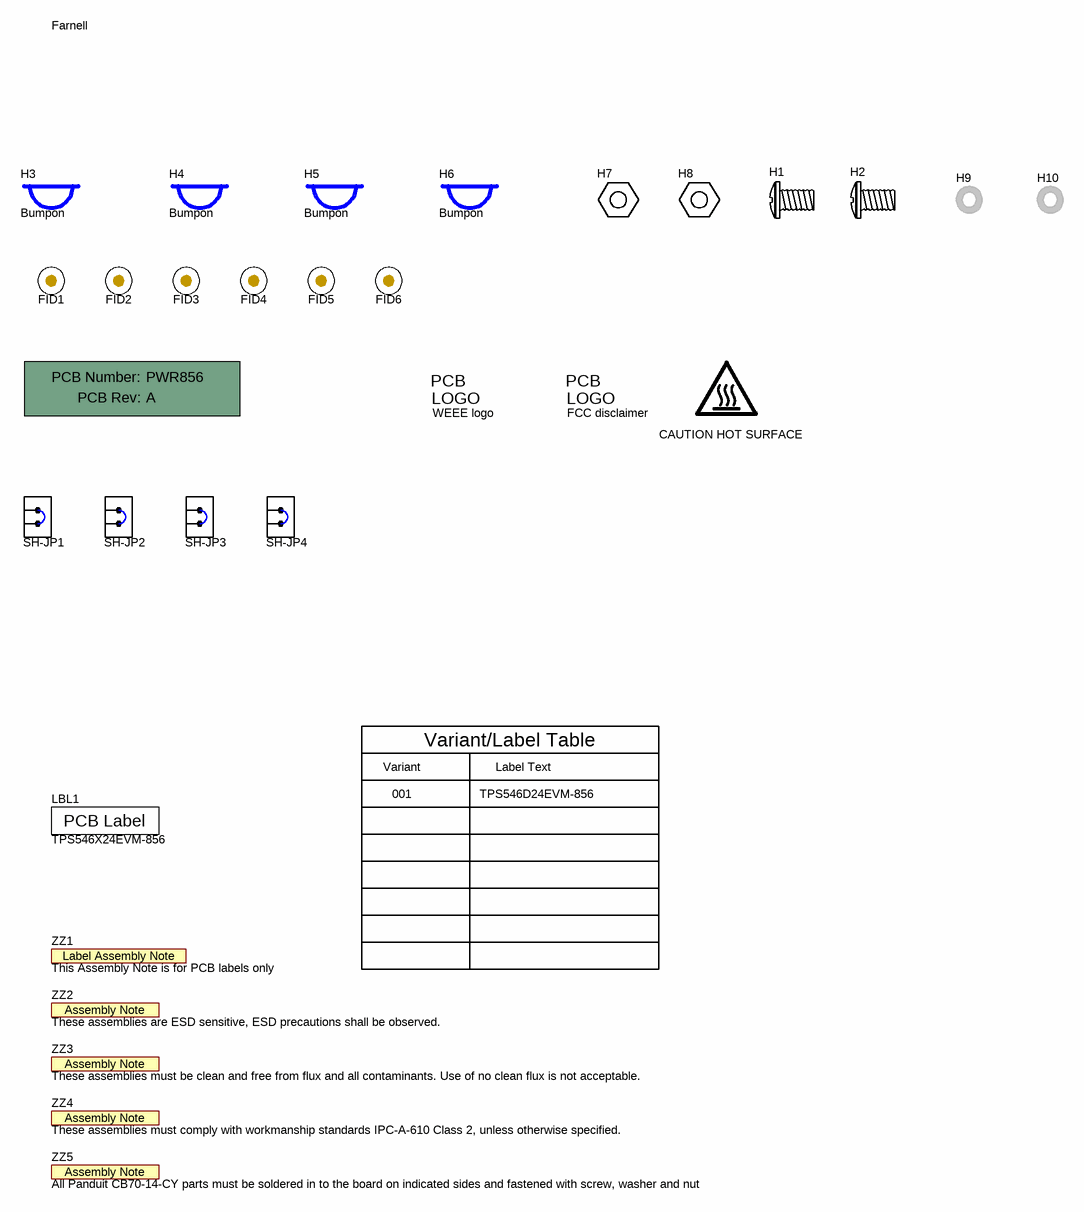
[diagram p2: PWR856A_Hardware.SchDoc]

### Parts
!PCB1  Printed Circuit Board  (value not drawn)  (mechanical)
FID1  Fiducial  [Fiducial10-20]  (value not drawn)
FID2  Fiducial  [Fiducial10-20]  (value not drawn)
FID3  Fiducial  [Fiducial10-20]  (value not drawn)
FID4  Fiducial  [Fiducial10-20]  (value not drawn)
FID5  Fiducial  [Fiducial10-20]  (value not drawn)
FID6  Fiducial  [Fiducial10-20]  (value not drawn)
H1  PMSSS 102 0050 PH  (value not drawn)  (mechanical)
H2  PMSSS 102 0050 PH  (value not drawn)  (mechanical)
H3  Bumpon  [Bumpon_SJ5003Transparent]
H4  Bumpon  [Bumpon_SJ5003Transparent]
H5  Bumpon  [Bumpon_SJ5003Transparent]
H6  Bumpon  [Bumpon_SJ5003Transparent]
H7  HNSS 102  (value not drawn)  (mechanical)
H8  HNSS 102  (value not drawn)  (mechanical)
H9  1477  (value not drawn)  (mechanical)
H10  1477  (value not drawn)  (mechanical)
LBL1  TPS546X24EVM-856  Supplier 2: Farnell  [Label_650x200]
Logo1  CAUTION HOT SURFACE  [IEC_HotSurface_Small]  (no BOM)
Logo4  WEEE logo  [WEEE_Minimum]  (no BOM)
Logo5  FCC disclaimer  [FCC_disclaimer]  (no BOM)
SH-JP1  969102-0000-DA  [SNT-100-BK-G]  (value not drawn)
SH-JP2  969102-0000-DA  [SNT-100-BK-G]  (value not drawn)
SH-JP3  969102-0000-DA  [SNT-100-BK-G]  (value not drawn)
SH-JP4  969102-0000-DA  [SNT-100-BK-G]  (value not drawn)
ZZ1  This Assembly Note is for PCB labels only  [AssemblyNoteLabel]  (no BOM)
ZZ2  These assemblies are ESD sensitive, ESD precautions shall be observed.  [AssemblyNote]  (no BOM)
ZZ3  These assemblies must be clean and free from flux and all contaminants. Use of no clean flux is not acceptable.  [AssemblyNote]  (no BOM)
ZZ4  These assemblies must comply with workmanship standards IPC-A-610 Class 2, unless otherwise specified.  [AssemblyNote]  (no BOM)
ZZ5  All Panduit CB70-14-CY parts must be soldered in to the board on indicated sides and fastened with screw, washer and nut  [AssemblyNote]  (no BOM)

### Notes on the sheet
- Variant
- Variant/Label Table
- Label Text
- 001
- TPS546D24EVM-856

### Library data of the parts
!PCB1 = CMP-0003618-2: Manufacturer: Any; PartNumber: PWR856
FID1-FID6 = CMP-0077181-1: Fiducial mark.  There is nothing to buy or mount.
H1 H2 = CMP-0081632-1: Machine Screw Pan Philips 10-32; Manufacturer: B&F Fastener Supply
H3-H6 = CMP-0003620-1: Bumpon, Hemisphere, 0.44 X 0.20, Clear; Manufacturer: 3M; PartNumber: SJ-5303 (CLEAR)
H7 H8 = CMP-0003731-1: Machine Screw Nut, Hex, 3/8', Stn, Steel, 10-32; Manufacturer: B&F Fastener Supply; CompType: Hardware
H9 H10 = CMP-0003748-1: Washer, Split Lock, #10; Manufacturer: Keystone; CompType: Lock Washer
LBL1 = CMP-0003625-1: Thermal Transfer Printable Labels, 0.650" W x 0.200" H - 10,000 per roll; Manufacturer: Brady; PartNumber: THT-14-423-10; Note: Size: 0.65" x 0.20 "
Logo1 = CMP-0074837-1: IEC 61010-1 Hot Surface Warning; SymbolCreator: a0412235
Logo4 = CMP-0074769-1
Logo5 = CMP-0074847-1: FCC_disclaimer
SH-JP1-SH-JP4 = 969102-0000-DA: Shunt, 100mil, Gold plated, Black; Manufacturer: 3M; Alternate Manufacturer: Samtec; Value: 1x2; Note: You can "mate" this to a header by matching the designator.  i.e. use SH-J3 for header J3; Green_Lifecycle: Active; Green_REACh: Passed
ZZ1 = CMP-0003616-3
ZZ2 = CMP-0077236-1
ZZ3 = CMP-0077237-1
ZZ4 = CMP-0077238-1
ZZ5 = AssemblyNote: This Assembly Note will show in the PcbDoc and associated outputs; SymbolCreator: codlsc

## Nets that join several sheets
GND: PWR856A_CoverSheet (86 pins), P1 (31 pins), P2 (31 pins)
Aux_5V: PWR856A_CoverSheet (5 pins), P1 (JP1_P1.1), P2 (JP1_P2.1)
AVIN: PWR856A_CoverSheet (7 pins), P1 (R2_P1.2), P2 (R2_P2.2)
CLK: PWR856A_CoverSheet (J2.9 TP10.1), P1 (R25_P1.2), P2 (R25_P2.2)
CNTL: PWR856A_CoverSheet (J2.7 TP9.1), P1 (JP2_P1.1), P2 (JP2_P2.1)
DATA: PWR856A_CoverSheet (J2.10 TP7.1), P1 (R23_P1.2), P2 (R23_P2.2)
EXT_SYNC: PWR856A_CoverSheet (TP27.1), P1 (R17_P1.1), P2 (R17_P2.1)
NetC17_P1_1: PWR856A_CoverSheet (R32.1), P1 (C17_P1.1 U1_P1.33)
NetC17_P1_2: PWR856A_CoverSheet (R33.1), P1 (C17_P1.2 R8_P1.2 U1_P1.34)
NetC17_P2_1: PWR856A_CoverSheet (R37.1), P2 (C17_P2.1 U1_P2.33)
NetC17_P2_2: PWR856A_CoverSheet (R39.1), P2 (C17_P2.2 R8_P2.2 U1_P2.34)
NetR15_P1_1: PWR856A_CoverSheet (TP21.1), P1 (R15_P1.1), P2 (R15_P2.1)
NetR16_P1_2: PWR856A_CoverSheet (TP31.1), P1 (R16_P1.2), P2 (R16_P2.2)
NetR22_P1_2: PWR856A_CoverSheet (TP29.1), P1 (R22_P1.2), P2 (R22_P2.2)
PG_Stack: P1 (R24_P1.1), P2 (R24_P2.1)
PVIN: PWR856A_CoverSheet (6 pins), P1 (16 pins), P2 (16 pins)
SMBALT: PWR856A_CoverSheet (J2.8 TP8.1), P1 (R27_P1.2), P2 (R27_P2.2)
SW_P1: PWR856A_CoverSheet (L1.1), P1 (8 pins)
SW_P2: PWR856A_CoverSheet (L2.1), P2 (8 pins)

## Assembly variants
001: not fitted C11_P1 C11_P2 C18_P1 C18_P2 C27 C28 C29 C30 C39 C40 C45 C46 C61 C62 C65 C66 C69 C70 C71 C72 FID1 FID2 FID3 FID4 FID5 FID6 J1 J3 R1_P1 R1_P2 R2_P1 R2_P2 R8_P1 R10_P1 R10_P2 R11_P1 R11_P2 R12_P1 R12_P2 R13_P2 R18_P1 R18_P2 R20_P1 R20_P2 R21_P2 R24_P1 R24_P2 R37 R39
